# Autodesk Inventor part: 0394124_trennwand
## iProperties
Created: 2005-08
Part Number: 0394124_trennwand
Document SubType Name: Modellieren
Manufacturer: Standard
Standards Organization: Custom
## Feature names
1. Basis1
